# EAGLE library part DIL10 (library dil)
SOCKET Dual In Line
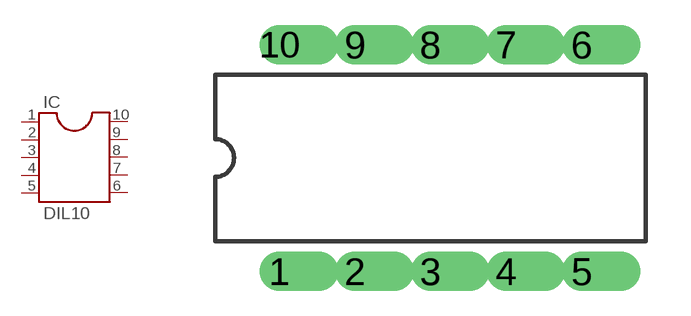
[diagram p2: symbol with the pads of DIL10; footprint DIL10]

Designator prefix IC

## DIL10  [DIL10]
1  1  pas
2  2  pas
3  3  pas
4  4  pas
5  5  pas
6  6  pas
7  7  pas
8  8  pas
9  9  pas
10  10  pas

## Footprint DIL10 (pad centres in mm)
SOCKET Dual In Line
drill 0.813 offset: 1 -5.08,-3.81; 2 -2.54,-3.81; 3 0,-3.81; 4 2.54,-3.81; 5 5.08,-3.81; 6 5.08,3.81; 7 2.54,3.81; 8 0,3.81; 9 -2.54,3.81; 10 -5.08,3.81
